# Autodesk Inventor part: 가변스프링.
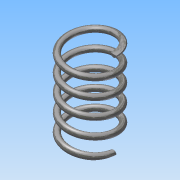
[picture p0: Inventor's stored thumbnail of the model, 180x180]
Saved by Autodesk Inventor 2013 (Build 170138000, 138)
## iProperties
Created: 2018-10
Part Number: 가변스프링.
Material: 스테인리스강
Document SubType Name: Modeling
Designer: Administrator
Density: 8.08 g/cm^3
Mass: 6.28631 g
Surface Area: 15.7888 cm^2
Volume: 0.778009 cm^3
Author: Administrator
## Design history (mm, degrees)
sketch "스케치1"
  geometry: L1 (0, 0)-(0, 29.23); L2 (0, 0)-(8, 0); L3 (0, 29.23)-(8, 29.23); C1 r 1 at (8, 0)
  constraints: 6 end point, 1 centre point, 1 coincident, 1 parallel, 1 perpendicular, 1 vertical
  dimensions: "d0" = 29.23004 distance of L1.start L1.end (derived); "d1" = 8 distance of L1.start L2.end; "d2" = 2 diameter of C1; "d3" = 8 distance of L1.end L3.end
feature "코일1" sketch "스케치1" pitch "d4" = 10; turns "d6" = 5; dims "d5" = 29.23004 (= d0), "d7" = 0, angle "d8" = 90 deg, angle "d9" = 90 deg, "d10" = 0, "d11" = 0
sketch "스케치2"
  geometry: L1 (29.23, 11)-(0, 11); L2 (0, 11)-(0, -11); L3 (0, -11)-(29.23, -11); L4 (29.23, -11)-(29.23, 11); 2 further points
  constraints: 8 end point, 2 parallel, 1 coincident, 1 horizontal, 1 midpoint, 1 perpendicular
  dimensions: "d12" = 29.23004 distance of L1.start L1.end (derived); "d14" = 22 distance of L3.end L1.start
extrude "돌출1" sketch "스케치2" stored distance "d15" = 0; taper "d16" = 0 deg
node "솔리드1"
